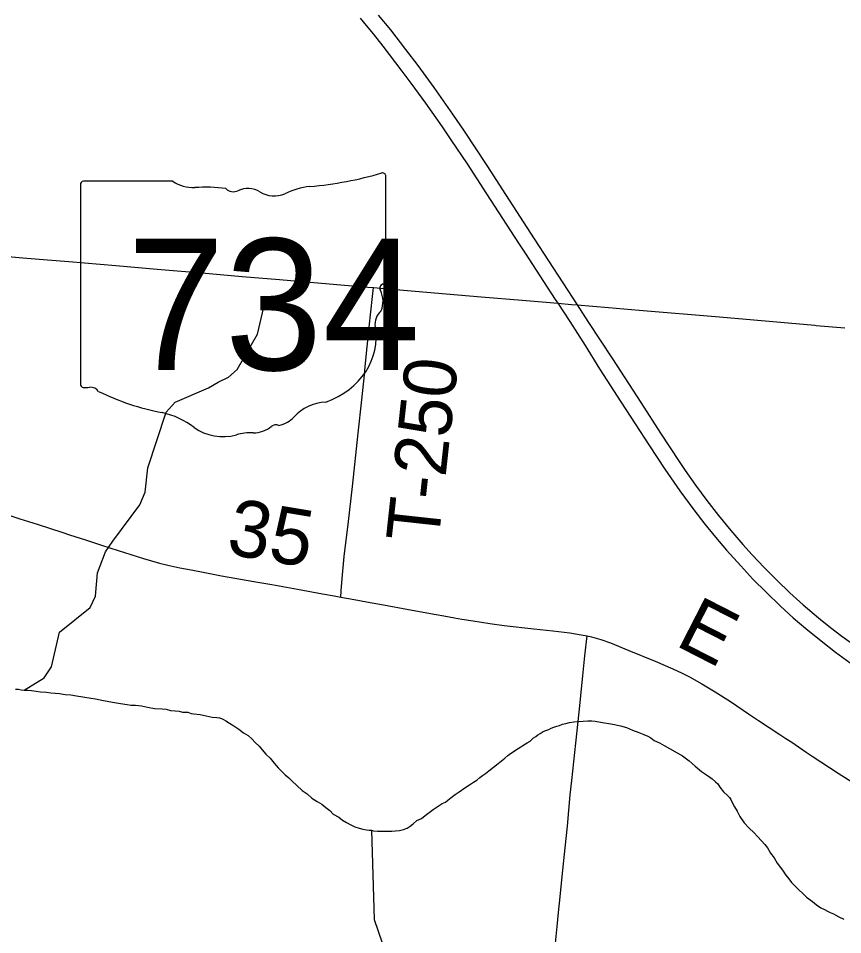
# Model space of a CAD drawing. Extents: x -13.9 to 69.1, y -25.2 to 26.1.
# Drawn here: x 5.691 to 6.483, y 16.946 to 17.826 of the extents above; entities that cross this region are included whole.
import ezdxf

# ---------------------------------------------------------------- set-up
doc = ezdxf.new("R2010")
doc.units = 0
for name, color, linetype in [('GM_X_County_Road', 7, 'Continuous'), ('GM_X_County_Road_Text', 7, 'Continuous'), ('GM_X_Minor_River', 7, 'Continuous'), ('GM_X_State_Location', 7, 'Continuous'), ('GM_X_State_Route', 7, 'Continuous'), ('GM_X_State_Shield', 7, 'Continuous'), ('GM_X_Township_Road', 7, 'Continuous'), ('GM_X_Township_Road_Text', 7, 'Continuous'), ('GM_X_US_Route', 7, 'Continuous')]:
    doc.layers.add(name, color=color, linetype=linetype)

msp = doc.modelspace()

# ---------------------------------------------------------------- linework, layer by layer
at = {"layer": 'GM_X_County_Road'}
for points in [[(5.67731, 17.35077), (5.69263, 17.34573), (5.70902, 17.34035), (5.73392, 17.33233), (5.74027, 17.33029), (5.75561, 17.32531), (5.77094, 17.32027), (5.78683, 17.31516), (5.81123, 17.30747), (5.82673, 17.30301), (5.83483, 17.30098), (5.84622, 17.29848), (5.85709, 17.29647), (5.8686, 17.29424), (5.88618, 17.29101), (5.91717, 17.28546), (5.92317, 17.2844), (5.93462, 17.28238), (5.95915, 17.278), (5.98313, 17.27364), (5.99456, 17.27153), (6.00071, 17.2704)], [(6.00071, 17.2704), (6.01363, 17.26803), (6.02561, 17.26588), (6.04195, 17.26291), (6.0659, 17.25855), (6.09258, 17.25364), (6.09968, 17.25242), (6.11005, 17.25063), (6.11713, 17.24938), (6.12806, 17.24749), (6.14393, 17.245), (6.15766, 17.24315), (6.18624, 17.23988), (6.2044, 17.23792), (6.22087, 17.23601), (6.23177, 17.23434), (6.23741, 17.23317)], [(6.20624, 16.92863), (6.20876, 16.95406), (6.21006, 16.96766), (6.21139, 16.98246), (6.21332, 17.00198), (6.21626, 17.02976), (6.21847, 17.05043), (6.22127, 17.0806), (6.2227, 17.0942), (6.22664, 17.13023), (6.22976, 17.15977), (6.23324, 17.19467), (6.23536, 17.21418), (6.23741, 17.23317)], [(6.23741, 17.23317), (6.24149, 17.23232), (6.25051, 17.22975), (6.2599, 17.22635), (6.27746, 17.21918), (6.30276, 17.20879), (6.31968, 17.20151), (6.3288, 17.1973), (6.33579, 17.1938), (6.34755, 17.18729), (6.36055, 17.17946), (6.37619, 17.16945), (6.39256, 17.15838), (6.40192, 17.15207), (6.42268, 17.13845), (6.42836, 17.13477), (6.43397, 17.131), (6.43725, 17.12882), (6.44798, 17.12152), (6.45362, 17.11777), (6.47871, 17.10148), (6.49432, 17.09134)]]:
    msp.add_lwpolyline(points, dxfattribs=at)
at = {"layer": 'GM_X_Minor_River'}
for points in [[(5.69666, 17.18108), (5.71583, 17.19282), (5.72309, 17.20358), (5.73072, 17.23688), (5.7601, 17.26029), (5.76535, 17.27146), (5.76706, 17.2936), (5.77481, 17.31381), (5.78173, 17.32421), (5.80793, 17.35896), (5.81285, 17.37122), (5.81559, 17.39444), (5.833, 17.44789), (5.84158, 17.45754), (5.87384, 17.47145), (5.88303, 17.47672), (5.89289, 17.48162), (5.90144, 17.48908), (5.92088, 17.52288), (5.92705, 17.54893)], [(5.68822, 17.18191), (5.69126, 17.18187), (5.69396, 17.18147), (5.69666, 17.18108), (5.70003, 17.18104), (5.70374, 17.18063), (5.70812, 17.18021), (5.7125, 17.17943), (5.71824, 17.179), (5.72228, 17.17858), (5.72633, 17.17817), (5.73072, 17.17775), (5.73611, 17.17696), (5.74151, 17.17653), (5.7469, 17.17574), (5.76105, 17.17339), (5.7651, 17.17261), (5.77116, 17.17145), (5.78161, 17.1695), (5.78936, 17.16832), (5.79576, 17.16715), (5.79913, 17.16674), (5.80352, 17.16669), (5.80925, 17.16589), (5.81531, 17.16473), (5.82172, 17.16356), (5.82914, 17.16311), (5.83319, 17.1627), (5.83722, 17.16156), (5.84161, 17.16114), (5.84565, 17.16073), (5.84868, 17.15996), (5.85172, 17.15993), (5.85375, 17.1599), (5.85711, 17.15877), (5.85981, 17.15837), (5.86588, 17.15757), (5.87161, 17.15641), (5.87733, 17.15525), (5.88172, 17.15483), (5.88441, 17.15444), (5.88609, 17.15369), (5.88811, 17.15294), (5.89046, 17.15146), (5.89381, 17.14923), (5.89818, 17.14664), (5.90287, 17.14367), (5.90722, 17.13998), (5.91192, 17.13738), (5.91527, 17.13443), (5.91861, 17.13075), (5.92229, 17.12743), (5.92529, 17.12376), (5.92897, 17.11971), (5.93298, 17.11566), (5.93698, 17.11089), (5.94065, 17.10648), (5.94433, 17.1028), (5.94734, 17.09985), (5.95102, 17.0969), (5.95369, 17.09396), (5.96373, 17.08474), (5.96842, 17.08141), (5.97311, 17.07736), (5.97814, 17.07402), (5.9825, 17.07142), (5.98652, 17.06847), (5.9902, 17.06551), (5.99354, 17.06183), (5.99892, 17.05922), (6.0026, 17.05627), (6.0063, 17.05404), (6.01032, 17.05181), (6.01436, 17.04995), (6.01839, 17.04844), (6.0221, 17.04767), (6.02547, 17.0469), (6.02816, 17.0465), (6.03019, 17.04648), (6.03221, 17.04609), (6.03592, 17.04568), (6.03862, 17.04565), (6.04132, 17.04562), (6.04537, 17.04557), (6.04976, 17.04552), (6.05347, 17.04583), (6.05719, 17.04615), (6.06091, 17.0472), (6.06464, 17.04861), (6.06736, 17.05039), (6.07042, 17.05254), (6.07383, 17.05577), (6.07823, 17.0579), (6.08198, 17.06076), (6.08572, 17.06363), (6.08946, 17.06649), (6.09422, 17.06971)], [(6.09422, 17.06971), (6.09829, 17.0722), (6.10134, 17.07362), (6.10372, 17.07541), (6.10679, 17.07792), (6.11053, 17.08078), (6.1146, 17.08328), (6.12004, 17.08721), (6.12446, 17.09007), (6.1282, 17.09257), (6.1316, 17.09471), (6.13432, 17.09723), (6.13704, 17.09901), (6.13976, 17.10116), (6.14316, 17.10366), (6.152, 17.11047), (6.15507, 17.11334), (6.15847, 17.11584), (6.1612, 17.11836), (6.16391, 17.12014), (6.1663, 17.12193), (6.16867, 17.12336), (6.17105, 17.12515), (6.17377, 17.12657), (6.17581, 17.128), (6.17818, 17.12943), (6.17988, 17.1305), (6.1826, 17.13192), (6.1843, 17.13372), (6.186, 17.13515), (6.18804, 17.13658), (6.19008, 17.13801), (6.19246, 17.13944), (6.19518, 17.14122), (6.19789, 17.14228), (6.2006, 17.14334), (6.20297, 17.1444), (6.20535, 17.14546), (6.2084, 17.14652), (6.21077, 17.14721), (6.21381, 17.14827), (6.21686, 17.14896), (6.22058, 17.15001), (6.22464, 17.15068), (6.22903, 17.15099), (6.23376, 17.1513), (6.23815, 17.15161), (6.24186, 17.15156), (6.24524, 17.15116), (6.25029, 17.15037), (6.254, 17.1496), (6.25838, 17.14918), (6.26377, 17.14803), (6.2695, 17.14687), (6.27522, 17.14534), (6.28094, 17.14273), (6.28699, 17.14047), (6.29203, 17.13859), (6.29573, 17.13673), (6.29875, 17.13524), (6.30177, 17.13266), (6.30681, 17.13041), (6.31151, 17.12781), (6.32897, 17.11814), (6.33533, 17.11334), (6.34136, 17.10817), (6.34738, 17.10301), (6.35207, 17.09968), (6.35543, 17.09746), (6.35744, 17.09598), (6.36079, 17.09302), (6.36313, 17.09118), (6.36479, 17.08789), (6.36846, 17.08348), (6.37213, 17.07979), (6.37414, 17.07795), (6.37547, 17.07612), (6.37713, 17.07246), (6.37912, 17.06916), (6.38144, 17.06477), (6.38409, 17.05965), (6.38842, 17.05378), (6.39309, 17.04863), (6.39744, 17.04421), (6.40111, 17.04053), (6.40479, 17.03648), (6.40813, 17.03281), (6.4108, 17.0295), (6.41345, 17.02438), (6.41712, 17.01997), (6.4201, 17.01484), (6.4231, 17.0108), (6.42577, 17.00714), (6.42843, 17.00347), (6.43109, 16.9998), (6.43376, 16.99649), (6.4371, 16.99281), (6.44814, 16.98213), (6.45384, 16.97806), (6.45785, 16.97474), (6.46188, 16.97215)], [(6.03019, 17.04648), (6.03296, 16.96086), (6.04807, 16.91694), (6.04824, 16.90676), (6.04567, 16.87337), (6.0301, 16.84968), (6.00267, 16.82187), (5.9988, 16.81213), (5.99695, 16.78163), (5.99375, 16.77152), (5.98518, 16.76296), (5.97992, 16.75107), (5.97364, 16.73811), (5.97793, 16.71221)], [(6.46188, 16.97215), (6.46557, 16.97028), (6.46826, 16.9688), (6.47095, 16.96767), (6.47397, 16.96618), (6.47632, 16.96506), (6.47934, 16.96321), (6.48405, 16.96097)]]:
    msp.add_lwpolyline(points, dxfattribs=at)
at = {"layer": 'GM_X_State_Route'}
for points in [[(5.67789, 17.59796), (5.69551, 17.59635), (5.71921, 17.59448), (5.73961, 17.59283), (5.78479, 17.58887), (5.82444, 17.58526), (5.87073, 17.5814), (5.906, 17.57839), (5.94182, 17.5754), (6.01178, 17.56928), (6.02684, 17.56805)], [(6.02684, 17.56805), (6.03216, 17.56762), (6.04981, 17.56617), (6.13575, 17.55872), (6.17489, 17.55556), (6.19798, 17.55358)], [(6.19798, 17.55358), (6.20916, 17.55262), (6.22228, 17.55149), (6.22796, 17.551), (6.25809, 17.54842), (6.28731, 17.54608), (6.36443, 17.53959), (6.456, 17.53143)], [(6.456, 17.53143), (6.45753, 17.53129), (6.48508, 17.52886)]]:
    msp.add_lwpolyline(points, dxfattribs=at)
at = {"layer": 'GM_X_State_Shield'}
for p, q in [((6.04396, 17.57437), (6.04396, 17.67457)), ((5.75076, 17.66653), (5.75076, 17.47498)), ((5.83951, 17.66982), (5.75365, 17.66982)), ((6.04394, 17.5744), (6.04396, 17.57437))]:
    msp.add_line(p, q, dxfattribs=at)
for centre, major_axis, start_param, end_param in [((5.93952, 17.93097), (0.31094, 0), 4.814394, 5.042369), ((6.04071, 17.67499), (0.00326, 0), 6.141152, 7.989035), ((5.75412, 17.66694), (0.0034, 0), 1.712693, 3.28349), ((5.85996, 17.69206), (0.03295, 0), 4.042523, 4.731795), ((5.87089, 17.56229), (0.11828, 0), 1.404758, 1.657858), ((5.89774, 17.66793), (0.0095, 0), 3.836095, 5.185415), ((5.91169, 17.64579), (0.01976, 0), 0.950623, 2.079405), ((5.97918, 17.61132), (0.06256, 0), 1.699011, 2.107814), ((5.9372, 17.67616), (0.02377, 0), 4.081561, 5.145723), ((6.04048, 17.57398), (0.00349, 0), 5.05454, 6.418171), ((6.04321, 17.56702), (0.00505, 0), 1.883978, 3.671073), ((6.01107, 17.55435), (0.03032, 0), 5.934695, 6.695948), ((6.05566, 17.53244), (0.02206, 0), 2.387724, 3.262537), ((5.95694, 17.51969), (0.07777, 0), 5.101752, 6.440018), ((5.75415, 17.47456), (0.00343, 0), 3.00124, 4.508301), ((5.75467, 17.49416), (0.02615, 0), 4.665946, 4.897461), ((5.76002, 17.46393), (0.00943, 0), 0.519207, 1.627899), ((5.87907, 17.63603), (0.22454, 0), 4.195997, 4.488961), ((5.98973, 17.42121), (0.04259, 0), 1.647645, 2.488434), ((5.81213, 17.38893), (0.07025, 0), 0.823519, 1.323587), ((5.93576, 17.45642), (0.02513, 0), 4.937069, 5.64225), ((5.88811, 17.46298), (0.04458, 0), 4.026481, 4.996735), ((5.91713, 17.44864), (0.02375, 0), 4.691044, 5.507374), ((5.93862, 17.43009), (0.00669, 0), 1.147584, 2.315152), ((5.91387, 17.39676), (0.03663, 0), 1.495662, 1.94098)]:
    msp.add_ellipse(centre, major_axis=major_axis, ratio=0.860726, start_param=start_param, end_param=end_param, dxfattribs=at)
at = {"layer": 'GM_X_Township_Road'}
for points in [[(6.02348, 17.48403), (6.02431, 17.49177), (6.02808, 17.52959), (6.03125, 17.5591), (6.03216, 17.56762)], [(6.00071, 17.2704), (6.00116, 17.27631), (6.00206, 17.28816), (6.00404, 17.30944), (6.00811, 17.34303), (6.01211, 17.37663), (6.01747, 17.42801), (6.02089, 17.45989), (6.02348, 17.48403)]]:
    msp.add_lwpolyline(points, dxfattribs=at)
at = {"layer": 'GM_X_US_Route'}
for points in [[(6.03677, 17.82938), (6.04844, 17.81509), (6.06305, 17.79647), (6.07491, 17.7808), (6.0902, 17.75971), (6.10817, 17.73409), (6.11922, 17.71775), (6.14097, 17.68478), (6.15899, 17.65698), (6.18656, 17.61458), (6.22796, 17.551), (6.23826, 17.53518), (6.26174, 17.49913), (6.28905, 17.45727), (6.30801, 17.42799), (6.32584, 17.40075), (6.33169, 17.39208), (6.34167, 17.37781), (6.35231, 17.36333), (6.36365, 17.34868), (6.37537, 17.3344), (6.38704, 17.32086), (6.39591, 17.31103), (6.40734, 17.29891), (6.41986, 17.28629), (6.43227, 17.27442), (6.44501, 17.26295), (6.45975, 17.25037), (6.47128, 17.2411), (6.48214, 17.23286), (6.49635, 17.22252)], [(6.01939, 17.82647), (6.02529, 17.81936), (6.03188, 17.81132), (6.04113, 17.79948), (6.05946, 17.77564), (6.06813, 17.76407), (6.0822, 17.74493), (6.09822, 17.72215), (6.10665, 17.70963), (6.12208, 17.6864), (6.14086, 17.6577), (6.17158, 17.61042), (6.17789, 17.60067), (6.19915, 17.56804), (6.20672, 17.55633), (6.2068, 17.5562)], [(6.2068, 17.5562), (6.20916, 17.55262), (6.22076, 17.53499), (6.23547, 17.51193), (6.24931, 17.4897), (6.26981, 17.45797), (6.29736, 17.41557), (6.31216, 17.39334), (6.32663, 17.37234), (6.33994, 17.35413), (6.35046, 17.34036), (6.36065, 17.32787), (6.37114, 17.31565), (6.38499, 17.30031), (6.39675, 17.28777), (6.40925, 17.27519), (6.42326, 17.26175), (6.43546, 17.2506), (6.44753, 17.24021), (6.46207, 17.22841), (6.47596, 17.21765), (6.49011, 17.20728)]]:
    msp.add_lwpolyline(points, dxfattribs=at)

# ---------------------------------------------------------------- texts
at = {"layer": 'GM_X_County_Road_Text'}
for s, height, rotation, p in [('35', 0.054296, 350.54631, (5.8898, 17.31204)), ('E', 0.05369, 332.91272, (6.32087, 17.22468))]:
    msp.add_text(s, height=height, rotation=rotation, dxfattribs=at).set_placement(p)
at = {"layer": 'GM_X_State_Location'}
for s in ['s', 'r']:
    msp.add_text(s, height=0.000181, dxfattribs=at).set_placement((5.89406, 17.55802))
msp.add_text('734', height=0.000181, rotation=0.00001, dxfattribs=at).set_placement((5.83459, 17.54483))
at = {"layer": 'GM_X_State_Shield'}
msp.add_text('734', height=0.126187, dxfattribs=at).set_placement((5.79553, 17.48849))
at = {"layer": 'GM_X_Township_Road_Text'}
msp.add_text('T-250', height=0.0506, rotation=83.76683, dxfattribs=at).set_placement((6.09447, 17.32151))

doc.saveas('drawing.dxf')
